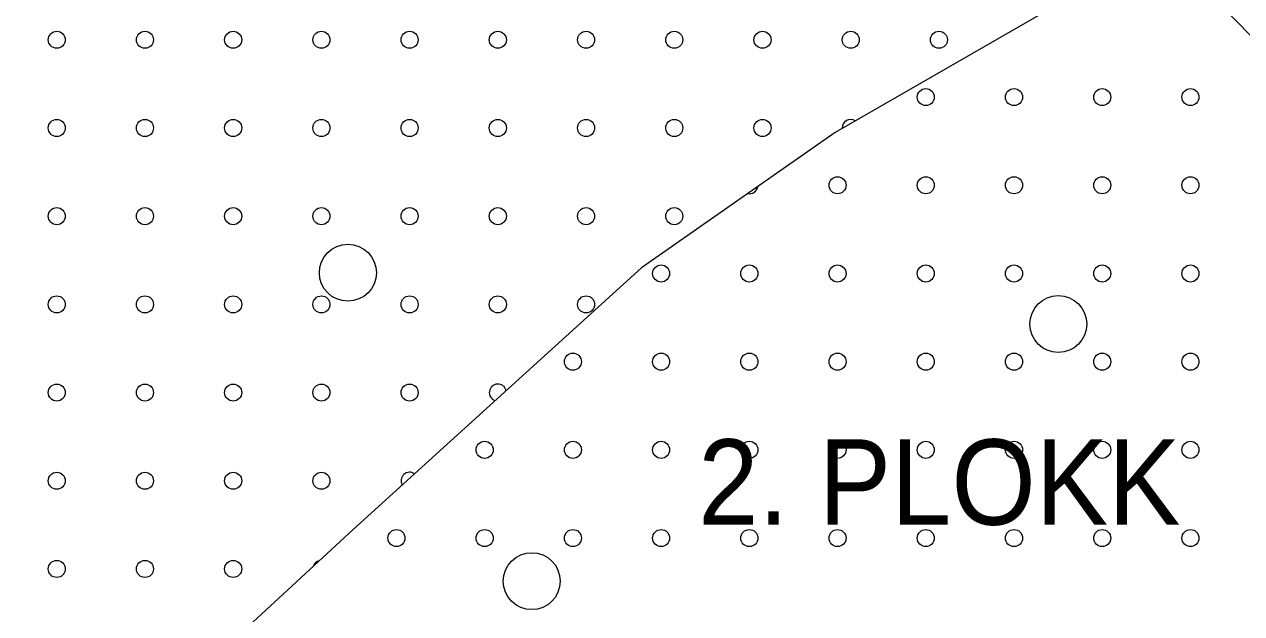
# Model space of a CAD drawing. Extents: x 640121 to 640955, y 6441885 to 6442246.
# Drawn here: x 640729.02 to 640771.79, y 6442139.22 to 6442159.94 of the extents above; entities that cross this region are included whole.
import ezdxf
from ezdxf.enums import TextEntityAlignment as Align

# ---------------------------------------------------------------- set-up
doc = ezdxf.new("R2010")
doc.units = 0
doc.header["$LTSCALE"] = 1.2
for name, color, linetype, lineweight in [('31', 7, 'Continuous', 13), ('35', 7, 'Continuous', 35), ('43', 7, 'Continuous', 13), ('47', 7, 'Continuous', 13)]:
    doc.layers.add(name, color=color, linetype=linetype, lineweight=lineweight)

msp = doc.modelspace()

# ---------------------------------------------------------------- linework, layer by layer
at = {"layer": '31'}
for points in [[(640766.2, 6442165.53), (640768.66, 6442162.89), (640770.97, 6442160.71), (640772.75, 6442158.89), (640774.15, 6442157.53), (640776.49, 6442155.56), (640779.68, 6442153.5), (640782.25, 6442152.37), (640783.6, 6442151.9), (640785.78, 6442151.67), (640789.26, 6442151.64), (640792.68, 6442151.97), (640796.68, 6442152.4), (640800.71, 6442152.95), (640806.66, 6442154.43), (640812.84, 6442155.93)], [(640768.87, 6442162.69), (640757.51, 6442156.14), (640750.7, 6442151.38), (640740.57, 6442142.18), (640734.45, 6442136.52), (640730.23, 6442132.58), (640726.39, 6442128.73), (640721.62, 6442123.48), (640717.7, 6442119.38), (640711.91, 6442113.06), (640707.64, 6442108.99), (640702.12, 6442104.54), (640697.95, 6442101.43), (640691.86, 6442097.28), (640685.68, 6442093.53), (640680.63, 6442090.4), (640672.14, 6442085.32), (640667.54, 6442082.46), (640661.43, 6442079.43)]]:
    msp.add_lwpolyline(points, dxfattribs=at)
at = {"layer": '43'}
for centre in [(640730.157, 6442159.395), (640733.257, 6442159.395), (640736.357, 6442159.395), (640739.457, 6442159.395), (640742.557, 6442159.395), (640745.657, 6442159.395), (640748.757, 6442159.395), (640751.857, 6442159.395), (640754.957, 6442159.395), (640758.057, 6442159.395), (640761.157, 6442159.395), (640760.694, 6442157.381), (640763.794, 6442157.381), (640766.894, 6442157.381), (640769.994, 6442157.381), (640730.157, 6442156.295), (640733.257, 6442156.295), (640736.357, 6442156.295), (640739.457, 6442156.295), (640742.557, 6442156.295), (640745.657, 6442156.295), (640748.757, 6442156.295), (640751.857, 6442156.295), (640754.957, 6442156.295), (640757.594, 6442154.281), (640760.694, 6442154.281), (640763.794, 6442154.281), (640766.894, 6442154.281), (640769.994, 6442154.281), (640730.157, 6442153.195), (640733.257, 6442153.195), (640736.357, 6442153.195), (640739.457, 6442153.195), (640742.557, 6442153.195), (640745.657, 6442153.195), (640748.757, 6442153.195), (640751.857, 6442153.195), (640751.394, 6442151.181), (640754.494, 6442151.181), (640757.594, 6442151.181), (640760.694, 6442151.181), (640763.794, 6442151.181), (640766.894, 6442151.181), (640769.994, 6442151.181), (640730.157, 6442150.095), (640733.257, 6442150.095), (640736.357, 6442150.095), (640739.457, 6442150.095), (640742.557, 6442150.095), (640745.657, 6442150.095), (640748.757, 6442150.095), (640748.294, 6442148.081), (640751.394, 6442148.081), (640754.494, 6442148.081), (640757.594, 6442148.081), (640760.694, 6442148.081), (640763.794, 6442148.081), (640766.894, 6442148.081), (640769.994, 6442148.081), (640730.157, 6442146.995), (640733.257, 6442146.995), (640736.357, 6442146.995), (640739.457, 6442146.995), (640742.557, 6442146.995), (640745.194, 6442144.981), (640748.294, 6442144.981), (640751.394, 6442144.981), (640754.494, 6442144.981), (640757.594, 6442144.981), (640760.694, 6442144.981), (640763.794, 6442144.981), (640766.894, 6442144.981), (640769.994, 6442144.981), (640730.157, 6442143.895), (640733.257, 6442143.895), (640736.357, 6442143.895), (640739.457, 6442143.895), (640742.094, 6442141.881), (640745.194, 6442141.881), (640748.294, 6442141.881), (640751.394, 6442141.881), (640754.494, 6442141.881), (640757.594, 6442141.881), (640760.694, 6442141.881), (640763.794, 6442141.881), (640766.894, 6442141.881), (640769.994, 6442141.881), (640730.157, 6442140.795), (640733.257, 6442140.795), (640736.357, 6442140.795)]:
    msp.add_circle(centre, 0.3, dxfattribs=at)
for centre, start, end in [((640758.057, 6442156.295), 57.8442, 182.1191), ((640754.494, 6442154.281), 257.3539, 352.5263), ((640745.657, 6442146.995), 13.9933, 250.4977), ((640742.557, 6442143.895), 55.4788, 209.0122), ((640739.457, 6442140.795), 104.1788, 161.3488)]:
    msp.add_arc(centre, 0.3, start, end, dxfattribs=at)
at = {"layer": '47'}
for centre in [(640740.387, 6442151.206), (640765.351, 6442149.402), (640746.849, 6442140.366)]:
    msp.add_circle(centre, 1, dxfattribs=at)

# ---------------------------------------------------------------- texts
at = {"layer": '35', "width": 0.95}
msp.add_text('2. PLOKK', height=3, dxfattribs=at).set_placement((640761.17, 6442142.35), align=Align.CENTER)

doc.saveas('drawing.dxf')
